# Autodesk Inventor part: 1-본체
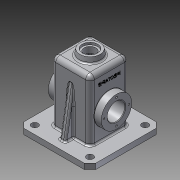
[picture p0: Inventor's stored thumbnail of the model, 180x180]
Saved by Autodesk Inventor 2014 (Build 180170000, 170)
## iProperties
Created: 2016-02
Part Number: 1-본체
Material: 알루미늄 6061
Document SubType Name: Modeling
Designer: S. S. MOON
Density: 2.71 g/cm^3
Appearance: 알루미늄 - 평지
Mass: 932.809 g
Surface Area: 1043.49 cm^2
Volume: 344.21 cm^3
Author: S. S. MOON
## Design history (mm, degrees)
sketch "스케치1"
  geometry: C1 r 27.5 at (0, 0); 1 further point
  constraints: 1 centre point, 1 coincident
  dimensions: "d0" = 55 diameter of C1
extrude "돌출1" new body sketch "스케치1" stored distance "d1" = 96; taper "d2" = 0 deg
sketch "스케치2"
  geometry: L1 (-35, 35)-(35, 35); L2 (35, 35)-(35, -35); L3 (35, -35)-(-35, -35); L4 (-35, -35)-(-35, 35); 3 further points
  constraints: 8 end point, 2 midpoint, 2 parallel, 1 horizontal, 1 horizontal alignment, 1 perpendicular, 1 vertical alignment
  dimensions: "d3" = 70 distance of L1.start L1.end; "d4" = 70 distance of L3.end L1.start
extrude "돌출2" join sketch "스케치2" distance "d5" = 55; taper "d6" = 0 deg
extrude "돌출3" join sketch "스케치2" distance "d7" = 65; taper "d8" = 0 deg
sketch "스케치3"
  geometry: C1 r 20 at (0, 0); 1 further point
  constraints: 1 centre point, 1 coincident
  dimensions: "d9" = 40 diameter of C1
extrude "돌출4" join sketch "스케치3" distance "d10" = 10; taper "d11" = -10 deg
sketch "스케치13"
  geometry: L1 (65, -65)-(-65, -65); L2 (-65, -65)-(-65, 65); L3 (-65, 65)-(65, 65); L4 (65, 65)-(65, -65); 3 further points
  constraints: 8 end point, 2 midpoint, 2 parallel, 1 horizontal, 1 horizontal alignment, 1 perpendicular, 1 vertical alignment
  dimensions: "d20" = 130 distance of L1.start L1.end; "d21" = 130 distance of L3.end L1.start
extrude "돌출7" join sketch "스케치13" distance "d22" = 10; taper "d23" = 0 deg
sketch "스케치14"
  geometry: L1 (-35, -45)-(35, -45) reference; L2 (35, -45)-(35, 65) reference; L3 (-35, 65)-(35, 65) reference; L4 (-35, 65)-(-35, -45) reference; L5 (-65, -55)-(65, -55) reference; L6 (30, 60)-(30, -55); L7 (-30, -55)-(-30, 60); L8 (-30, 60)-(30, 60); 1 further point
  constraints: 6 end point, 2 point on line, 1 vertical, 1 other
  dimensions: "d25" = 5 distance between parallel lines of L4 L7; "d26" = 5 distance between parallel lines of L2 L6
extrude "돌출8" cut sketch "스케치14" stored distance "d27" = 60; taper "d28" = 0 deg
sketch "스케치15"
  geometry: L1 (23, -27.5)-(30, -27.5); L2 (30, -27.5)-(30, 0); L3 (30, 0)-(23, 0); L4 (23, 0)-(23, -27.5); L5 (48, -27.5)-(35, -27.5) reference; L6 (30, -55)-(30, 60) reference; L7 (30, -27.5)-(23, -20.5); 2 further points
  constraints: 10 end point, 2 collinear, 2 parallel, 1 horizontal, 1 horizontal alignment, 1 midpoint, 1 perpendicular, 1 point on line
  dimensions: "d30" = 7 distance between parallel lines of L4 L2; "d31" = 135 deg angle of L6 L7
revolve "회전1" sketch "스케치15" stored, may be unused: angle "d32" = 90 deg
hole "구멍1" diameter "d35" = 21; stored, may be unused: countersink angle "d39" = 90 deg, drill point angle "d41" = 118 deg; dims "d36" = 6, "d37" = 28, "d38" = 4, "d40" = 21, "d95" = 10, "d96" = 10
hole "구멍2" diameter "d44" = 32; stored, may be unused: countersink angle "d48" = 90 deg, drill point angle "d50" = 118 deg; dims "d42" = 10, "d43" = 10, "d45" = 6, "d46" = 25, "d47" = 4, "d49" = 21
sketch "스케치16"
  geometry: L1 (0, 0)-(-22.5, 0)
  constraints: 2 end point, 1 horizontal
  dimensions: "d51" = 22.5 distance of L1.start L1.end
hole "구멍3" sketch "스케치16" at (0, 0), (-22.5, 0) diameter "d52" = 3.242; stored, may be unused: countersink angle "d56" = 90 deg, drill point angle "d58" = 118 deg; dims "d53" = 8, "d54" = 25, "d55" = 4, "d57" = 10
sketch "스케치17"
  geometry: L1 (-50, -50)-(50, -50); L2 (50, -50)-(50, 50); L3 (50, 50)-(-50, 50); L4 (-50, 50)-(-50, -50); 3 further points
  constraints: 8 end point, 2 midpoint, 2 parallel, 1 horizontal, 1 horizontal alignment, 1 perpendicular, 1 vertical alignment
  dimensions: "d62" = 100 distance of L3.end L1.start; "d63" = 100 distance of L1.start L1.end
hole "구멍4" sketch "스케치17" at (-50, -50), (50, 50), (50, -50), (-50, 50) diameter "d64" = 12; stored, may be unused: countersink angle "d68" = 90 deg, drill point angle "d70" = 118 deg; dims "d65" = 12, "d66" = 25, "d67" = 4, "d69" = 10
sketch "스케치18"
  geometry: L1 (-50, -45)-(-35, 40.069); L2 (-35, 65)-(-35, -45) reference; L3 (-56, -45)-(-44, -45) reference; L4 (65, -45)-(-65, -45) reference; L5 (-65, -55)-(-65, -45) reference; 1 further point
  constraints: 2 end point, 2 point on line
  dimensions: "d71" = 15 distance from line of L5 L1.start; "d72" = 10 deg angle of L5 L1
extrude "돌출9" join sketch "스케치18" stored distance "d73" = 10; taper "d74" = 0 deg
fillet "모깎기1" dims "d75" = 0.5
fillet "모깎기2" dims "d76" = 3
fillet "모깎기3" dims "d77" = 3
fillet "모깎기4" dims "d78" = 3
chamfer "모따기1" distance "d80" = 1; stored, may be unused: second distance "d81" = 2, angle "d82" = 45 deg
chamfer "모따기2" distance "d83" = 10; stored, may be unused: second distance "d84" = 2, angle "d85" = 45 deg
fillet "모깎기7" dims "d87" = 8
fillet "모깎기8" dims "d88" = 8
fillet "모깎기9" dims "d89" = 0.5
fillet "모깎기10" dims "d90" = 3
fillet "모깎기11" dims "d91" = 3
fillet "모깎기12" dims "d92" = 3
fillet "모깎기13" dims "d93" = 3
fillet "모깎기14" dims "d94" = 3
sketch "스케치19"
  geometry: L1 (99, 62)-(0, 62) reference; L2 (21.916, 5.803)-(21.916, 48.197); L3 (21.916, 48.197)-(2.084, 48.197); L4 (2.084, 48.197)-(2.084, 5.803); L5 (2.084, 5.803)-(21.916, 5.803); L6 (-18, 8.763)-(-18, 45.237) reference; 3 further points
  constraints: 2 midpoint, 1 horizontal, 2 other
  dimensions: "d98" = 35 distance from line of L1 point (21.916, 27); "d99" = 30 distance from line of L6 point (12, 5.803)
feature "엠보싱1" sketch "스케치19" dims "d0" = 55, "d100" = 0.5, "d101" = 0
node "솔리드1"
mirror "대칭1"
pattern_circular "원형 패턴1" dims angle "d60" = 360 deg
mirror "대칭2"
mirror "대칭3"
node "투영된 루프2"
